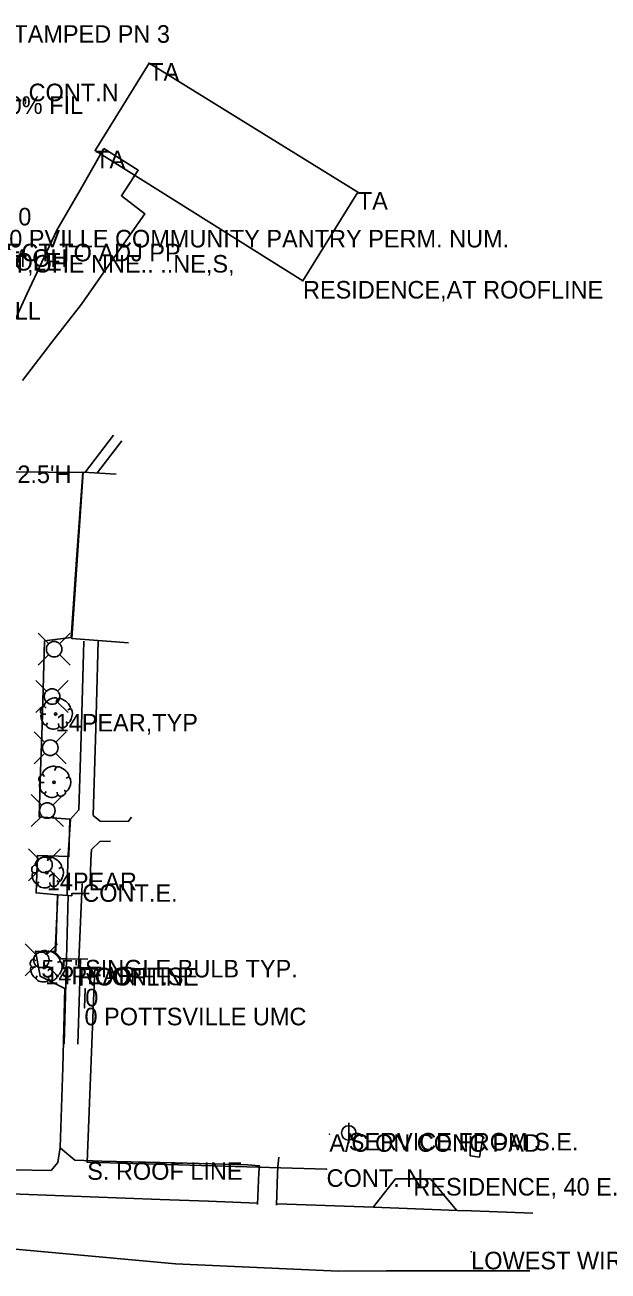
# Model space of a CAD drawing. Extents: x 997398 to 1003416, y 334596 to 337085.
# Drawn here: x 999337.6 to 999503.6, y 335281.5 to 335636.2 of the extents above; entities that cross this region are included whole.
import ezdxf

# ---------------------------------------------------------------- set-up
doc = ezdxf.new("R2010")
doc.units = 0
for name, color, linetype in [('S_BUILDING', 7, 'Continuous'), ('S_BUILDING_ANNOT', 7, 'Continuous'), ('S_CURB', 7, 'Continuous'), ('S_EDGE_CONCRETE', 7, 'Continuous'), ('S_EDGE_PAVEMENT', 7, 'Continuous'), ('S_ELECTRIC_UTILITIES_ANNOT', 7, 'Continuous'), ('S_FENCE_ANNOT', 7, 'Continuous'), ('S_FIBER_OPTIC_CABLE_ANNOT', 7, 'Continuous'), ('S_GAS_UTILITIES_ANNOT', 7, 'Continuous'), ('S_GRD_PT_SYM', 7, 'Continuous'), ('S_MANHOLE_ANNOT', 7, 'Continuous'), ('S_MISC_STRUCTURES_ANNOT', 7, 'Continuous'), ('S_MSC_PT_SYM', 7, 'Continuous'), ('S_PAVEMENT_CROWN', 7, 'Continuous'), ('S_PRIMARY_CTL_ANNOT', 7, 'Continuous'), ('S_SIDE_DRAIN_ANNOT', 7, 'Continuous'), ('S_SIDEWALK', 7, 'Continuous'), ('S_SIGN', 7, 'Continuous'), ('S_SIGN_ANNOT', 7, 'Continuous'), ('S_STR_PT_SYM', 7, 'Continuous'), ('S_SURVEY_TEXT_ANNOT', 7, 'Continuous'), ('S_TREE', 7, 'Continuous'), ('S_TREE_ANNOT', 7, 'Continuous'), ('S_UTILITY_POLE', 7, 'Continuous'), ('S_UTILITY_POLE_ANNOT', 7, 'Continuous'), ('S_UTL_PT_SYM', 7, 'Continuous')]:
    doc.layers.add(name, color=color, linetype=linetype)

msp = doc.modelspace()

# ---------------------------------------------------------------- linework, layer by layer
at = {"layer": 'S_BUILDING'}
for p, q in [((999373, 335625.32), (999357.62, 335600.41)), ((999373, 335625.32), (999432.39, 335588.63)), ((999416.78, 335563.32), (999357.62, 335600.41)), ((999432.39, 335588.63), (999416.78, 335563.32)), ((999352.87, 335367.78), (999353.97, 335391.61)), ((999357.49, 335367.87), (999352.87, 335367.78)), ((999355.37, 335312.49), (999357.49, 335367.87)), ((999355.37, 335312.49), (999423.49, 335310.48))]:
    msp.add_line(p, q, dxfattribs=at)
at = {"layer": 'S_CURB'}
for points in [[(999403.71, 335300.85), (999389.91, 335301.36), (999376.11, 335301.88), (999356.19, 335302.64), (999336.26, 335303.4), (999320.74, 335304), (999306.07, 335304.52), (999296.29, 335305.51), (999286.68, 335308.77), (999280.16, 335311.86), (999275.88, 335314.72), (999271.24, 335318.89), (999269.34, 335320.89)], [(999482.16, 335297.97), (999464.76, 335298.65), (999460.78, 335298.73), (999436.88, 335299.68), (999431.39, 335299.85), (999409.39, 335300.64)]]:
    msp.add_lwpolyline(points, dxfattribs=at)
at = {"layer": 'S_EDGE_CONCRETE'}
for points in [[(999363.65, 335508.33), (999354.17, 335508.93), (999352.56, 335485.25), (999350.95, 335461.56), (999367.08, 335460.3)], [(999349.31, 335370.4), (999348.03, 335370.39), (999346.28, 335372.31), (999346.98, 335388.6), (999349.88, 335388.45)], [(999355.54, 335370.26), (999349.46, 335370.38), (999349.99, 335388.4), (999350.95, 335388.33), (999350.96, 335388.97), (999355.93, 335388.96)], [(999460.46, 335298.87), (999453.05, 335307.73), (999443.12, 335307.79), (999436.85, 335299.77)]]:
    msp.add_lwpolyline(points, dxfattribs=at)
at = {"layer": 'S_EDGE_PAVEMENT'}
for points in [[(999360.1, 335600.98), (999369.89, 335594.81), (999365.08, 335587.57), (999371.75, 335582.47), (999362.75, 335569.59), (999353.74, 335556.7), (999345.33, 335545.87), (999336.92, 335535.03)], [(999346.76, 335577.82), (999353.43, 335589.4), (999360.1, 335600.98)], [(999329.71, 335541.35), (999338.23, 335559.58), (999346.76, 335577.82)], [(999333.12, 335509.03), (999344.25, 335508.86), (999354.13, 335508.83), (999352.46, 335485.33), (999350.79, 335461.83), (999343.21, 335460.89), (999342.55, 335436.79), (999342.11, 335423.79), (999341.68, 335410.8), (999350.45, 335410.1), (999350.15, 335399.48), (999341.22, 335399.8), (999340.83, 335389.13), (999346.93, 335388.61), (999346.4, 335372.49), (999340.63, 335372.54), (999342.02, 335365.44), (999348.99, 335361.96), (999348.46, 335339.49), (999347.71, 335316.72), (999347, 335312.43), (999345.08, 335310.18), (999333.98, 335310.31)]]:
    msp.add_lwpolyline(points, dxfattribs=at)
at = {"layer": 'S_GRD_PT_SYM'}
msp.add_lwpolyline([(999464.65, 335287.01), (999464.65, 335287.06), (999464.65, 335287.01), (999464.6, 335287.01), (999464.65, 335287.01), (999464.65, 335286.96), (999464.65, 335287.01), (999464.7, 335287.01)], dxfattribs=at)
at = {"layer": 'S_MSC_PT_SYM'}
for points in [[(999354.81, 335361.86), (999354.81, 335361.91), (999354.81, 335361.86), (999354.76, 335361.86), (999354.81, 335361.86), (999354.81, 335361.81), (999354.81, 335361.86), (999354.86, 335361.86)], [(999354.59, 335356.46), (999354.59, 335356.51), (999354.59, 335356.46), (999354.54, 335356.46), (999354.59, 335356.46), (999354.59, 335356.41), (999354.59, 335356.46), (999354.64, 335356.46)], [(999424.28, 335320.46), (999424.28, 335320.51), (999424.28, 335320.46), (999424.23, 335320.46), (999424.28, 335320.46), (999424.28, 335320.41), (999424.28, 335320.46), (999424.33, 335320.46)], [(999448.19, 335308), (999448.19, 335308.05), (999448.19, 335308), (999448.14, 335308), (999448.19, 335308), (999448.19, 335307.95), (999448.19, 335308), (999448.24, 335308)]]:
    msp.add_lwpolyline(points, dxfattribs=at)
at = {"layer": 'S_PAVEMENT_CROWN'}
msp.add_lwpolyline([(999481.36, 335281.6), (999467.73, 335281.58), (999454.1, 335281.56), (999440.47, 335281.53), (999426.85, 335281.51), (999403.67, 335282.53), (999380.49, 335283.56), (999357.71, 335285.65), (999334.94, 335287.74), (999314.61, 335289.19), (999300.25, 335290.16), (999285.89, 335291.13), (999270.7, 335292.19), (999255.51, 335293.25)], dxfattribs=at)
at = {"layer": 'S_SIDEWALK'}
for points in [[(999362.82, 335519.45), (999354.84, 335508.98)], [(999365.24, 335517.86), (999358.28, 335508.82)], [(999349.66, 335388.6), (999349.89, 335398.51), (999350.57, 335410.15), (999353.02, 335412.77), (999353.72, 335436.78), (999354.41, 335460.79)], [(999358.52, 335460.81), (999357.79, 335436), (999357.06, 335411.19), (999359.01, 335409.58), (999367, 335409.43), (999367.94, 335410.67)], [(999362.03, 335403.9), (999358.98, 335403.74), (999356.61, 335401.49), (999356.41, 335398.52), (999356.22, 335391.24)], [(999348.79, 335346.22), (999349.49, 335370.29)], [(999352.7, 335346.12), (999353.45, 335370.19)], [(999464.48, 335320.02), (999464.4, 335314.31), (999466.97, 335313.97), (999468.03, 335319.84)], [(999403.79, 335300.44), (999404.23, 335309.61), (999404.37, 335311.47), (999401.11, 335311.75), (999380.33, 335312.27), (999359.54, 335312.79), (999351.87, 335313.05), (999347.74, 335316.5)], [(999409.25, 335300.25), (999409.53, 335309.2), (999409.58, 335311.21), (999409.94, 335313.97)]]:
    msp.add_lwpolyline(points, dxfattribs=at)
at = {"layer": 'S_SIGN'}
msp.add_line((999354.59, 335356.46), (999354.81, 335361.86), dxfattribs=at)
at = {"layer": 'S_STR_PT_SYM'}
for points in [[(999373, 335625.32), (999373, 335625.37), (999373, 335625.32), (999372.95, 335625.32), (999373, 335625.32), (999373, 335625.27), (999373, 335625.32), (999373.05, 335625.32)], [(999357.62, 335600.41), (999357.62, 335600.46), (999357.62, 335600.41), (999357.57, 335600.41), (999357.62, 335600.41), (999357.62, 335600.36), (999357.62, 335600.41), (999357.67, 335600.41)], [(999432.39, 335588.63), (999432.39, 335588.68), (999432.39, 335588.63), (999432.34, 335588.63), (999432.39, 335588.63), (999432.39, 335588.58), (999432.39, 335588.63), (999432.44, 335588.63)], [(999416.78, 335563.32), (999416.78, 335563.37), (999416.78, 335563.32), (999416.73, 335563.32), (999416.78, 335563.32), (999416.78, 335563.27), (999416.78, 335563.32), (999416.83, 335563.32)], [(999353.97, 335391.61), (999353.97, 335391.66), (999353.97, 335391.61), (999353.92, 335391.61), (999353.97, 335391.61), (999353.97, 335391.56), (999353.97, 335391.61), (999354.02, 335391.61)], [(999352.87, 335367.78), (999352.87, 335367.83), (999352.87, 335367.78), (999352.82, 335367.78), (999352.87, 335367.78), (999352.87, 335367.73), (999352.87, 335367.78), (999352.92, 335367.78)], [(999357.49, 335367.87), (999357.49, 335367.92), (999357.49, 335367.87), (999357.44, 335367.87), (999357.49, 335367.87), (999357.49, 335367.82), (999357.49, 335367.87), (999357.54, 335367.87)], [(999355.37, 335312.49), (999355.37, 335312.54), (999355.37, 335312.49), (999355.32, 335312.49), (999355.37, 335312.49), (999355.37, 335312.44), (999355.37, 335312.49), (999355.42, 335312.49)], [(999423.49, 335310.48), (999423.49, 335310.53), (999423.49, 335310.48), (999423.44, 335310.48), (999423.49, 335310.48), (999423.49, 335310.43), (999423.49, 335310.48), (999423.54, 335310.48)]]:
    msp.add_lwpolyline(points, dxfattribs=at)
at = {"layer": 'S_TREE'}
for p, q in [((999346.93, 335444.34), (999346.54, 335443.49)), ((999343.13, 335442.32), (999343.64, 335441.74)), ((999350.5, 335441.55), (999349.84, 335441.28)), ((999342.47, 335440), (999343.6, 335440)), ((999343.64, 335436.82), (999344.1, 335437.52)), ((999347.32, 335436.55), (999347.24, 335437.32)), ((999349.72, 335437.44), (999349.26, 335437.87)), ((999342.69, 335422.86), (999343.2, 335422.28)), ((999346.49, 335424.87), (999346.1, 335424.02)), ((999342.04, 335420.53), (999343.16, 335420.53)), ((999350.06, 335422.08), (999349.4, 335421.81)), ((999343.2, 335417.36), (999343.66, 335418.05)), ((999346.88, 335417.09), (999346.8, 335417.86)), ((999349.28, 335417.98), (999348.82, 335418.4)), ((999344.42, 335399.16), (999344.04, 335398.31)), ((999339.97, 335394.82), (999341.09, 335394.82)), ((999340.63, 335397.15), (999341.13, 335396.56)), ((999347.99, 335396.37), (999347.33, 335396.1)), ((999341.13, 335391.64), (999341.6, 335392.34)), ((999344.81, 335391.37), (999344.73, 335392.15)), ((999347.21, 335392.26), (999346.75, 335392.69)), ((999340.2, 335370.37), (999340.71, 335369.79)), ((999344, 335372.38), (999343.61, 335371.53)), ((999347.57, 335369.59), (999346.91, 335369.32)), ((999339.54, 335368.04), (999340.67, 335368.04)), ((999340.71, 335364.87), (999341.17, 335365.56)), ((999344.39, 335364.59), (999344.31, 335365.37)), ((999346.79, 335365.49), (999346.33, 335365.91))]:
    msp.add_line(p, q, dxfattribs=at)
for centre in [(999346.37, 335440.09), (999345.93, 335420.63), (999343.87, 335394.92), (999343.44, 335368.14)]:
    msp.add_circle(centre, 0.341, dxfattribs=at)
for centre, major_axis, ratio, start_param, end_param in [((999345.04, 335443.29), (1.86, 1.08), 0.471018, 0, 3.141593), ((999348.69, 335442.97), (-1.81, 1.36), 0.405113, 3.141593, 6.283186), ((999342.8, 335441.18), (0.31, 1.03), 0.646762, 0, 3.141593), ((999350.05, 335439.56), (0.46, 2.04), 0.482994, 3.141593, 6.283185), ((999343.11, 335438.53), (-0.61, 1.6), 0.420543, 6.283185, 9.424777), ((999345.57, 335436.75), (-1.83, 0.19), 0.529943, 0, 3.141593), ((999348.52, 335437.04), (1.09, 0.46), 0.711534, 3.141592, 6.283185), ((999342.36, 335421.72), (0.31, 1.03), 0.646762, 0, 3.141593), ((999344.6, 335423.83), (1.86, 1.08), 0.471018, 0, 3.141593), ((999348.25, 335423.51), (-1.81, 1.36), 0.405113, 3.141593, 6.283186), ((999342.67, 335419.07), (-0.61, 1.6), 0.420543, 6.283185, 9.424777), ((999349.61, 335420.1), (0.46, 2.04), 0.482994, 3.141593, 6.283185), ((999345.13, 335417.29), (-1.83, 0.19), 0.529943, 0, 3.141593), ((999348.09, 335417.58), (1.09, 0.46), 0.711534, 3.141592, 6.283185), ((999342.53, 335398.12), (1.86, 1.08), 0.471018, 0, 3.141593), ((999346.18, 335397.79), (-1.81, 1.36), 0.405113, 3.141593, 6.283186), ((999340.3, 335396), (0.31, 1.03), 0.646762, 0, 3.141593), ((999340.6, 335393.35), (-0.61, 1.6), 0.420543, 6.283185, 9.424777), ((999347.54, 335394.39), (0.46, 2.04), 0.482994, 3.141593, 6.283185), ((999343.06, 335391.57), (-1.83, 0.19), 0.529943, 0, 3.141593), ((999346.02, 335391.86), (1.09, 0.46), 0.711534, 3.141592, 6.283185), ((999339.87, 335369.23), (0.31, 1.03), 0.646762, 0, 3.141593), ((999342.11, 335371.34), (1.86, 1.08), 0.471018, 0, 3.141593), ((999345.76, 335371.02), (-1.81, 1.36), 0.405113, 3.141593, 6.283186), ((999347.12, 335367.61), (0.46, 2.04), 0.482994, 3.141593, 6.283185), ((999340.18, 335366.57), (-0.61, 1.6), 0.420543, 6.283185, 9.424777), ((999342.64, 335364.79), (-1.83, 0.19), 0.529943, 0, 3.141593), ((999345.59, 335365.09), (1.09, 0.46), 0.711534, 3.141592, 6.283185)]:
    msp.add_ellipse(centre, major_axis=major_axis, ratio=ratio, start_param=start_param, end_param=end_param, dxfattribs=at)
at = {"layer": 'S_UTILITY_POLE'}
for p, q in [((999344.35, 335460.09), (999341.37, 335463.07)), ((999347.53, 335460.09), (999350.52, 335463.07)), ((999344.35, 335456.91), (999341.37, 335453.93)), ((999347.53, 335456.91), (999350.52, 335453.93)), ((999343.77, 335446.61), (999340.79, 335449.6)), ((999346.95, 335446.61), (999349.93, 335449.6)), ((999343.77, 335443.44), (999340.79, 335440.45)), ((999346.95, 335443.44), (999349.93, 335440.45)), ((999343.25, 335432.04), (999340.27, 335435.02)), ((999346.43, 335432.04), (999349.42, 335435.02)), ((999343.25, 335428.86), (999340.27, 335425.88)), ((999346.43, 335428.86), (999349.42, 335425.88)), ((999342.42, 335414.16), (999339.43, 335417.14)), ((999345.59, 335414.16), (999348.58, 335417.14)), ((999342.42, 335410.98), (999339.43, 335408)), ((999345.59, 335410.98), (999348.58, 335408)), ((999341.63, 335398.7), (999338.64, 335401.69)), ((999344.8, 335398.7), (999347.79, 335401.69)), ((999341.63, 335395.53), (999338.64, 335392.54)), ((999344.8, 335395.53), (999347.79, 335392.54)), ((999340.72, 335371.66), (999337.73, 335374.64)), ((999343.89, 335371.66), (999346.88, 335374.64)), ((999340.72, 335368.48), (999337.73, 335365.5)), ((999343.89, 335368.48), (999346.88, 335365.5)), ((999429.8, 335317.9), (999429.8, 335323.69))]:
    msp.add_line(p, q, dxfattribs=at)
for centre, radius in [((999345.95, 335458.51), 2.21), ((999345.37, 335445.03), 2.21), ((999344.85, 335430.46), 2.21), ((999344.01, 335412.58), 2.21), ((999343.22, 335397.12), 2.21), ((999342.31, 335370.08), 2.21), ((999429.8, 335320.83), 2.05)]:
    msp.add_circle(centre, radius, dxfattribs=at)
at = {"layer": 'S_UTL_PT_SYM'}
msp.add_lwpolyline([(999464.65, 335287.01), (999464.65, 335287.06), (999464.65, 335287.01), (999464.6, 335287.01), (999464.65, 335287.01), (999464.65, 335286.96), (999464.65, 335287.01), (999464.7, 335287.01)], dxfattribs=at)

# ---------------------------------------------------------------- texts
at = {"layer": 'S_BUILDING_ANNOT'}
for s, p in [('TA', (999373, 335620.32)), ('TA', (999357.62, 335595.41)), ('TA ', (999432.39, 335583.63)), ('RESIDENCE,AT ROOFLINE', (999416.78, 335558.32)), ('CONT.E.', (999353.97, 335386.61)), ('ROOFLINE', (999352.87, 335362.78)), ('CONT.S.', (999357.49, 335362.87)), ('S. ROOF LINE', (999355.37, 335307.49)), ('CONT. N.', (999423.49, 335305.48))]:
    msp.add_text(s, height=5, dxfattribs=at).set_placement(p)
at = {"layer": 'S_ELECTRIC_UTILITIES_ANNOT'}
msp.add_text('LOWEST WIRE', height=5, dxfattribs=at).set_placement((999464.65, 335282.01))
at = {"layer": 'S_FENCE_ANNOT'}
msp.add_text('3"PIPE RAIL,2.5\'H', height=5, dxfattribs=at).set_placement((999295.57, 335505.8))
at = {"layer": 'S_FIBER_OPTIC_CABLE_ANNOT'}
msp.add_text('CONDUIT FROM OH', height=5, dxfattribs=at).set_placement((999285.88, 335567.34))
at = {"layer": 'S_GAS_UTILITIES_ANNOT'}
msp.add_text('1CALL SEZ DED LINE CONT S 1CALL', height=5, dxfattribs=at).set_placement((999224.76, 335552.3))
at = {"layer": 'S_MANHOLE_ANNOT'}
msp.add_text('TY:CONC BOTTOM OF MANHOLE', height=5, dxfattribs=at).set_placement((999241.48, 335566.28))
at = {"layer": 'S_MISC_STRUCTURES_ANNOT'}
msp.add_text('A/C ON CONC PAD', height=5, dxfattribs=at).set_placement((999424.28, 335315.46))
at = {"layer": 'S_PRIMARY_CTL_ANNOT'}
msp.add_text('PD:AHTD STD. MON. STAMPED PN 3', height=5, dxfattribs=at).set_placement((999262.27, 335631.12))
at = {"layer": 'S_SIDE_DRAIN_ANNOT'}
for s, p in [('DI:18 TY:RCP CN:50% FILL,CONT.N', (999252.48, 335614.48)), ('DI:24 TY:CMP,CRUSHED CN:50% FIL', (999237.91, 335610.88))]:
    msp.add_text(s, height=5, dxfattribs=at).set_placement(p)
at = {"layer": 'S_SIGN_ANNOT'}
for s, p in [('0', (999335.75, 335579.13)), ('0 PVILLE COMMUNITY PANTRY PERM. NUM.', (999333.17, 335572.86)), ('0', (999354.81, 335356.86)), ('0 POTTSVILLE UMC', (999354.59, 335351.46))]:
    msp.add_text(s, height=5, dxfattribs=at).set_placement(p)
at = {"layer": 'S_SURVEY_TEXT_ANNOT'}
msp.add_text('RESIDENCE, 40 E.ASH', height=5, dxfattribs=at).set_placement((999448.19, 335303))
at = {"layer": 'S_TREE_ANNOT'}
for s, p in [('14PEAR,TYP', (999346.37, 335435.09)), ('14PEAR', (999343.87, 335389.92)), ('14PEAR', (999343.44, 335363.14))]:
    msp.add_text(s, height=5, dxfattribs=at).set_placement(p)
at = {"layer": 'S_UTILITY_POLE_ANNOT'}
for s, p in [('1COND.,CONNECT TO ADJ PP', (999285.37, 335568.91)), ('1LGT,3CONDUIT,OHE NNE.. ..NE,S,', (999285.49, 335565.71)), ("5.5' SINGLE BULB TYP.", (999342.31, 335365.08)), ('SERVICE FROM S.E.', (999429.8, 335315.83))]:
    msp.add_text(s, height=5, dxfattribs=at).set_placement(p)

doc.saveas('drawing.dxf')
